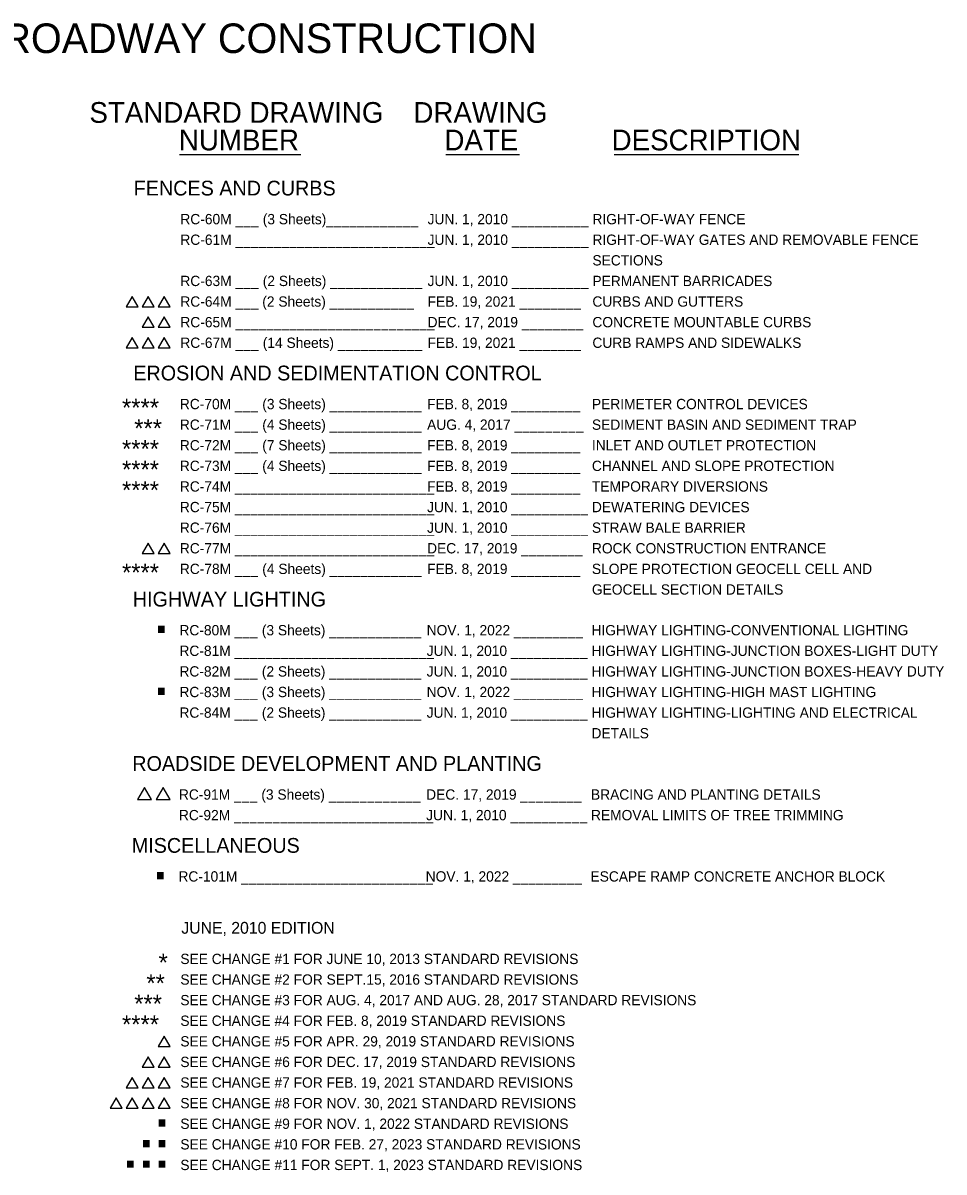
# Model space of a CAD drawing. Extents: x 0.08 to 2.68, y 0.04 to 1.72.
# Drawn here: x 1.387 to 2.684, y 0.107 to 1.725 of the extents above; entities that cross this region are included whole.
import ezdxf

# ---------------------------------------------------------------- set-up
doc = ezdxf.new("R2010")
doc.units = 0
doc.layers.add('Default', color=7, linetype='Continuous')
doc.layers.add('PLT-BNDY', color=7, linetype='Continuous')

msp = doc.modelspace()

# ---------------------------------------------------------------- linework, layer by layer
at = {"layer": 'PLT-BNDY'}
for p, q in [((1.6076, 1.5393), (1.7784, 1.5393)), ((1.9828, 1.5393), (2.0864, 1.5393)), ((2.2193, 1.5393), (2.4793, 1.5393))]:
    msp.add_line(p, q, dxfattribs=at)
for points in [[(1.5412, 1.3398), (1.5328, 1.3253), (1.5495, 1.3253)], [(1.5636, 1.3398), (1.5552, 1.3253), (1.572, 1.3253)], [(1.586, 1.3398), (1.5777, 1.3253), (1.5944, 1.3253)], [(1.5636, 1.3108), (1.5552, 1.2963), (1.572, 1.2963)], [(1.586, 1.3108), (1.5777, 1.2963), (1.5944, 1.2963)], [(1.5412, 1.2818), (1.5328, 1.2673), (1.5495, 1.2673)], [(1.5636, 1.2818), (1.5552, 1.2673), (1.572, 1.2673)], [(1.586, 1.2818), (1.5777, 1.2673), (1.5944, 1.2673)], [(1.5636, 0.9925), (1.5552, 0.978), (1.572, 0.978)], [(1.586, 0.9925), (1.5777, 0.978), (1.5944, 0.978)], [(1.5585, 0.6483), (1.5487, 0.6314), (1.5682, 0.6314)], [(1.5847, 0.6483), (1.5749, 0.6314), (1.5944, 0.6314)], [(1.586, 0.2985), (1.5777, 0.284), (1.5944, 0.284)], [(1.5636, 0.2695), (1.5552, 0.255), (1.572, 0.255)], [(1.586, 0.2695), (1.5777, 0.255), (1.5944, 0.255)], [(1.5412, 0.2405), (1.5328, 0.226), (1.5495, 0.226)], [(1.5636, 0.2405), (1.5552, 0.226), (1.572, 0.226)], [(1.586, 0.2405), (1.5777, 0.226), (1.5944, 0.226)], [(1.5187, 0.2115), (1.5103, 0.197), (1.5271, 0.197)], [(1.5412, 0.2115), (1.5328, 0.197), (1.5495, 0.197)], [(1.5636, 0.2115), (1.5552, 0.197), (1.572, 0.197)], [(1.586, 0.2115), (1.5777, 0.197), (1.5944, 0.197)]]:
    msp.add_lwpolyline(points, close=True, dxfattribs=at)

# ---------------------------------------------------------------- texts
at = {"layer": 'Default'}
for s, p in [('RC-60M ___', (1.6089, 1.4413)), ('(3 Sheets)____________', (1.7249, 1.4413)), ('JUN. 1, 2010 __________', (1.9569, 1.4413)), ('RIGHT-OF-WAY FENCE', (2.1889, 1.4413)), ('RC-61M __________________________', (1.6089, 1.4123)), ('JUN. 1, 2010 __________', (1.9569, 1.4123)), ('RIGHT-OF-WAY GATES AND REMOVABLE FENCE', (2.1889, 1.4123)), ('SECTIONS', (2.1889, 1.3833)), ('RC-63M ___', (1.6089, 1.3543)), ('(2 Sheets) ____________', (1.7249, 1.3543)), ('JUN. 1, 2010 __________', (1.9569, 1.3543)), ('PERMANENT BARRICADES', (2.1889, 1.3543)), ('RC-64M ___ (2 Sheets) ___________', (1.6089, 1.3253)), ('FEB. 19, 2021 ________', (1.9569, 1.3253)), ('CURBS AND GUTTERS', (2.1889, 1.3253)), ('RC-65M __________________________', (1.6089, 1.2963)), ('DEC. 17, 2019 ________', (1.9569, 1.2963)), ('CONCRETE MOUNTABLE CURBS', (2.1889, 1.2963)), ('RC-67M ___', (1.6089, 1.2673)), ('(14 Sheets) ___________', (1.7249, 1.2673)), ('FEB. 19, 2021 ________', (1.9569, 1.2673)), ('CURB RAMPS AND SIDEWALKS', (2.1889, 1.2673)), ('RC-70M ___', (1.6082, 1.181)), ('(3 Sheets) ____________', (1.7242, 1.181)), ('FEB. 8, 2019 _________', (1.9562, 1.181)), ('PERIMETER CONTROL DEVICES', (2.1882, 1.181)), ('RC-71M ___', (1.6082, 1.152)), ('(4 Sheets) ____________', (1.7242, 1.152)), ('AUG. 4, 2017 _________', (1.9562, 1.152)), ('SEDIMENT BASIN AND SEDIMENT TRAP', (2.1882, 1.152)), ('RC-72M ___', (1.6082, 1.123)), ('(7 Sheets) ____________', (1.7242, 1.123)), ('FEB. 8, 2019 _________', (1.9562, 1.123)), ('INLET AND OUTLET PROTECTION', (2.1882, 1.123)), ('RC-73M ___', (1.6082, 1.094)), ('(4 Sheets) ____________', (1.7242, 1.094)), ('FEB. 8, 2019 _________', (1.9562, 1.094)), ('CHANNEL AND SLOPE PROTECTION', (2.1882, 1.094)), ('RC-74M __________________________', (1.6082, 1.065)), ('FEB. 8, 2019 _________', (1.9562, 1.065)), ('TEMPORARY DIVERSIONS', (2.1882, 1.065)), ('RC-75M __________________________', (1.6082, 1.036)), ('JUN. 1, 2010 __________', (1.9562, 1.036)), ('DEWATERING DEVICES', (2.1882, 1.036)), ('RC-76M __________________________', (1.6082, 1.007)), ('JUN. 1, 2010 __________', (1.9562, 1.007)), ('STRAW BALE BARRIER', (2.1882, 1.007)), ('RC-77M __________________________', (1.6082, 0.978)), ('DEC. 17, 2019 ________', (1.9562, 0.978)), ('ROCK CONSTRUCTION ENTRANCE', (2.1882, 0.978)), ('RC-78M ___', (1.6082, 0.949)), ('(4 Sheets) ____________', (1.7242, 0.949)), ('FEB. 8, 2019 _________', (1.9562, 0.949)), ('SLOPE PROTECTION GEOCELL CELL AND', (2.1882, 0.949)), ('GEOCELL SECTION DETAILS', (2.1882, 0.92)), ('■', (1.5761, 0.8647)), ('RC-80M ___', (1.6076, 0.8627)), ('(3 Sheets) ____________', (1.7236, 0.8627)), ('NOV. 1, 2022 _________', (1.9556, 0.8627)), ('HIGHWAY LIGHTING-CONVENTIONAL LIGHTING', (2.1876, 0.8627)), ('RC-81M __________________________', (1.6076, 0.8337)), ('JUN. 1, 2010 __________', (1.9556, 0.8337)), ('HIGHWAY LIGHTING-JUNCTION BOXES-LIGHT DUTY', (2.1876, 0.8337)), ('RC-82M ___', (1.6076, 0.8047)), ('(2 Sheets) ____________', (1.7236, 0.8047)), ('JUN. 1, 2010 __________', (1.9556, 0.8047)), ('HIGHWAY LIGHTING-JUNCTION BOXES-HEAVY DUTY', (2.1876, 0.8047)), ('■', (1.5761, 0.7777)), ('RC-83M ___', (1.6076, 0.7757)), ('(3 Sheets) ____________', (1.7236, 0.7757)), ('NOV. 1, 2022 _________', (1.9556, 0.7757)), ('HIGHWAY LIGHTING-HIGH MAST LIGHTING', (2.1876, 0.7757)), ('RC-84M ___', (1.6076, 0.7467)), ('(2 Sheets) ____________', (1.7236, 0.7467)), ('JUN. 1, 2010 __________', (1.9556, 0.7467)), ('HIGHWAY LIGHTING-LIGHTING AND ELECTRICAL', (2.1876, 0.7467)), ('DETAILS', (2.1876, 0.7177)), ('RC-91M ___', (1.6069, 0.6314)), ('(3 Sheets) ____________', (1.7229, 0.6314)), ('DEC. 17, 2019 ________', (1.9549, 0.6314)), ('BRACING AND PLANTING DETAILS', (2.1869, 0.6314)), ('RC-92M __________________________', (1.6069, 0.6024)), ('JUN. 1, 2010 __________', (1.9549, 0.6024)), ('REMOVAL LIMITS OF TREE TRIMMING', (2.1869, 0.6024)), ('■', (1.5747, 0.5181)), ('RC-101M _________________________', (1.6062, 0.5161)), ('NOV. 1, 2022 _________', (1.9542, 0.5161)), ('ESCAPE RAMP CONCRETE ANCHOR BLOCK', (2.1862, 0.5161)), ('■', (1.5774, 0.17)), ('■', (1.555, 0.141)), ('■', (1.5774, 0.141)), ('■', (1.5325, 0.112)), ('■', (1.555, 0.112)), ('■', (1.5774, 0.112))]:
    msp.add_text(s, height=0.0145, dxfattribs=at).set_placement(p)
at = {"layer": 'PLT-BNDY'}
for s, height, p in [('INDEX OF STANDARDS FOR ROADWAY CONSTRUCTION', 0.041667, (0.5875, 1.6823)), ('STANDARD DRAWING', 0.029167, (1.4809, 1.5841)), ('DRAWING', 0.02917, (1.9369, 1.5841)), ('NUMBER', 0.02917, (1.6068, 1.5453)), ('DATE', 0.02917, (1.9806, 1.5453)), ('DESCRIPTION', 0.029167, (2.2159, 1.5453)), ('FENCES AND CURBS', 0.0208, (1.5432, 1.4818)), ('EROSION AND SEDIMENTATION CONTROL', 0.0208, (1.5426, 1.2215)), ('****', 0.025, (1.5268, 1.1707)), ('***', 0.025, (1.544, 1.1417)), ('****', 0.025, (1.5268, 1.1127)), ('****', 0.025, (1.5268, 1.0837)), ('****', 0.025, (1.5268, 1.0547)), ('****', 0.025, (1.5268, 0.9387)), ('HIGHWAY LIGHTING', 0.0208, (1.5419, 0.9032)), ('ROADSIDE DEVELOPMENT AND PLANTING', 0.0208, (1.5412, 0.6719)), ('MISCELLANEOUS', 0.0208, (1.5405, 0.5566)), ('JUNE, 2010 EDITION', 0.0166, (1.6103, 0.4427)), ('*', 0.025, (1.5783, 0.3897)), ('SEE CHANGE #1 FOR JUNE 10, 2013 STANDARD REVISIONS', 0.0145, (1.6089, 0.4)), ('**', 0.025, (1.5611, 0.3607)), ('SEE CHANGE #2 FOR SEPT.15, 2016 STANDARD REVISIONS', 0.0145, (1.6089, 0.371)), ('***', 0.025, (1.544, 0.3317)), ('SEE CHANGE #3 FOR AUG. 4, 2017 AND AUG. 28, 2017 STANDARD REVISIONS', 0.0145, (1.6089, 0.342)), ('****', 0.025, (1.5268, 0.3027)), ('SEE CHANGE #4 FOR FEB. 8, 2019 STANDARD REVISIONS', 0.0145, (1.6089, 0.313)), ('SEE CHANGE #5 FOR APR. 29, 2019 STANDARD REVISIONS', 0.0145, (1.6089, 0.284)), ('SEE CHANGE #6 FOR DEC. 17, 2019 STANDARD REVISIONS', 0.0145, (1.6089, 0.255)), ('SEE CHANGE #7 FOR FEB. 19, 2021 STANDARD REVISIONS', 0.0145, (1.6089, 0.226)), ('SEE CHANGE #8 FOR NOV. 30, 2021 STANDARD REVISIONS', 0.0145, (1.6089, 0.197)), ('SEE CHANGE #9 FOR NOV. 1, 2022 STANDARD REVISIONS', 0.0145, (1.6089, 0.168)), ('SEE CHANGE #10 FOR FEB. 27, 2023 STANDARD REVISIONS', 0.0145, (1.6089, 0.139)), ('SEE CHANGE #11 FOR SEPT. 1, 2023 STANDARD REVISIONS', 0.0145, (1.6089, 0.11))]:
    msp.add_text(s, height=height, dxfattribs=at).set_placement(p)

doc.saveas('drawing.dxf')
